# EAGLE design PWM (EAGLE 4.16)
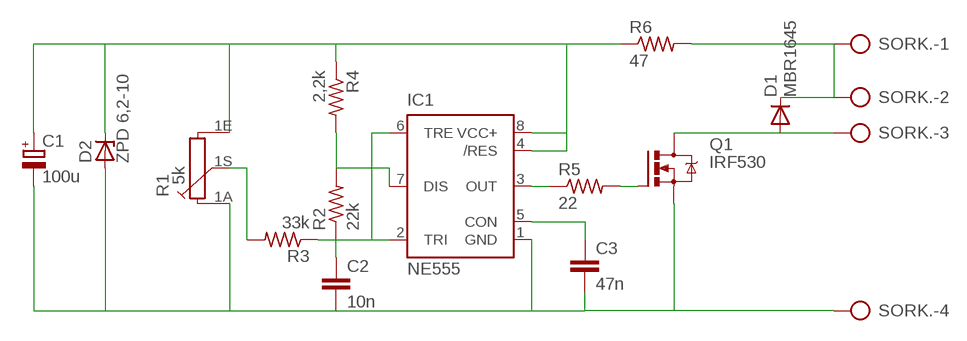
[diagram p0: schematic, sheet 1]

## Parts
C1  100u  CPOL-EUE5-13  [E5-13]
C2  10n  C-EU050-035X075  [C050-035X075]
C3  47n  C-EU050-035X075  [C050-035X075]
D1  MBR1645  MBR750  [TO220AC]
D2  ZPD 6,2-10  ZPD  [DO35Z10]
IC1  NE555  [DIL-08]
Q1  IRF530  [TO220BV]
R1  5k  PC16S  [PC16S]
R2  22k  R-US_0204/7  [0204/7]
R3  33k  R-US_0204/7  [0204/7]
R4  2,2k  R-US_0204/7  [0204/7]
R5  22  R-US_0204/7  [0204/7]
R6  47  R-US_0204/7  [0204/7]
SORK.  AK300/4  [AK300/4]

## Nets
N$1: IC1.7(DIS) R2.2 R4.2
N$3: D1.C R6.2 SORK..1 SORK..2
N$4: D1.A Q1.D SORK..3
N$5: C2.1 IC1.2(TRI) IC1.6(TRE) R2.1 R3.1
N$6: R1.1S R3.2
N$7: C1.- C2.2 C3.2 D2.A IC1.1(GND) Q1.S R1.1A SORK..4
N$8: IC1.3(OUT) R5.1
N$9: Q1.G R5.2
N$10: C3.1 IC1.5(CON)
N$12: C1.+ D2.C IC1.4(/RES) IC1.8(VCC+) R1.1E R4.1 R6.1

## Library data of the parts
C1 = rcl:CPOL-EU: POLARIZED CAPACITOR, European symbol
C2 C3 = rcl:C-EU: CAPACITOR, European symbol
D1 = diode:MBR750: DIODE
D2 = diode:ZPD: Z DIODE
IC1 = st-microelectronics:NE555: General purpose bipolar Timer
Q1 = transistor-power:IRF530: HEXFET Power MOSFET
R1 = piher:PC16S: POTENTIOMETER single carbon potentiometer, 16 mm, S3ROH
R2-R6 = rcl:R-US_: RESISTOR, American symbol
SORK. = con-ptr500:AK300/4: CONNECTOR

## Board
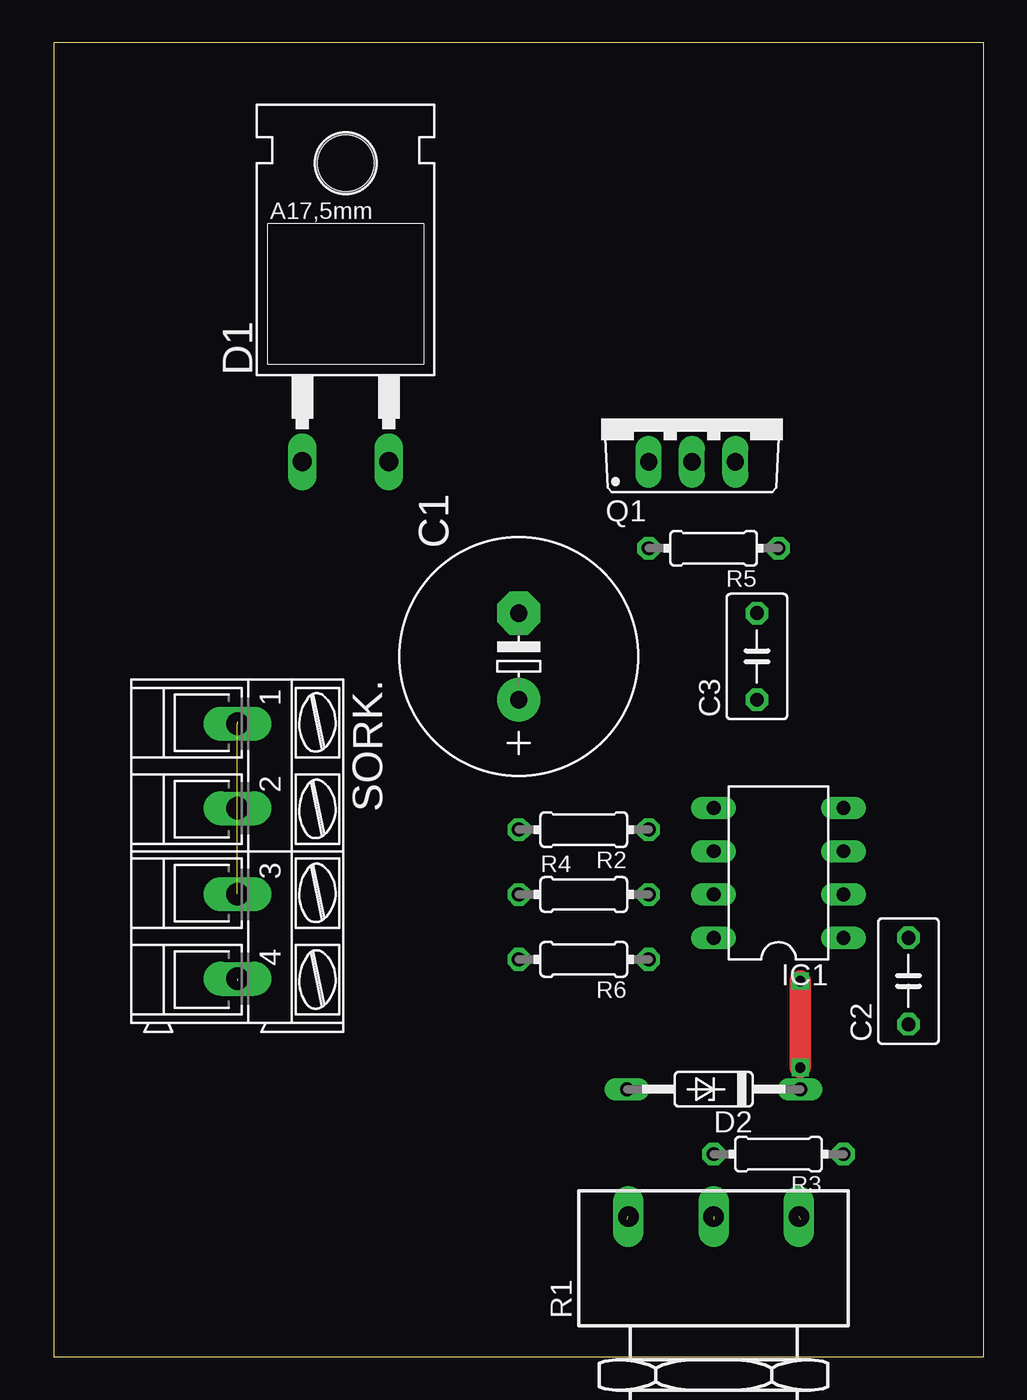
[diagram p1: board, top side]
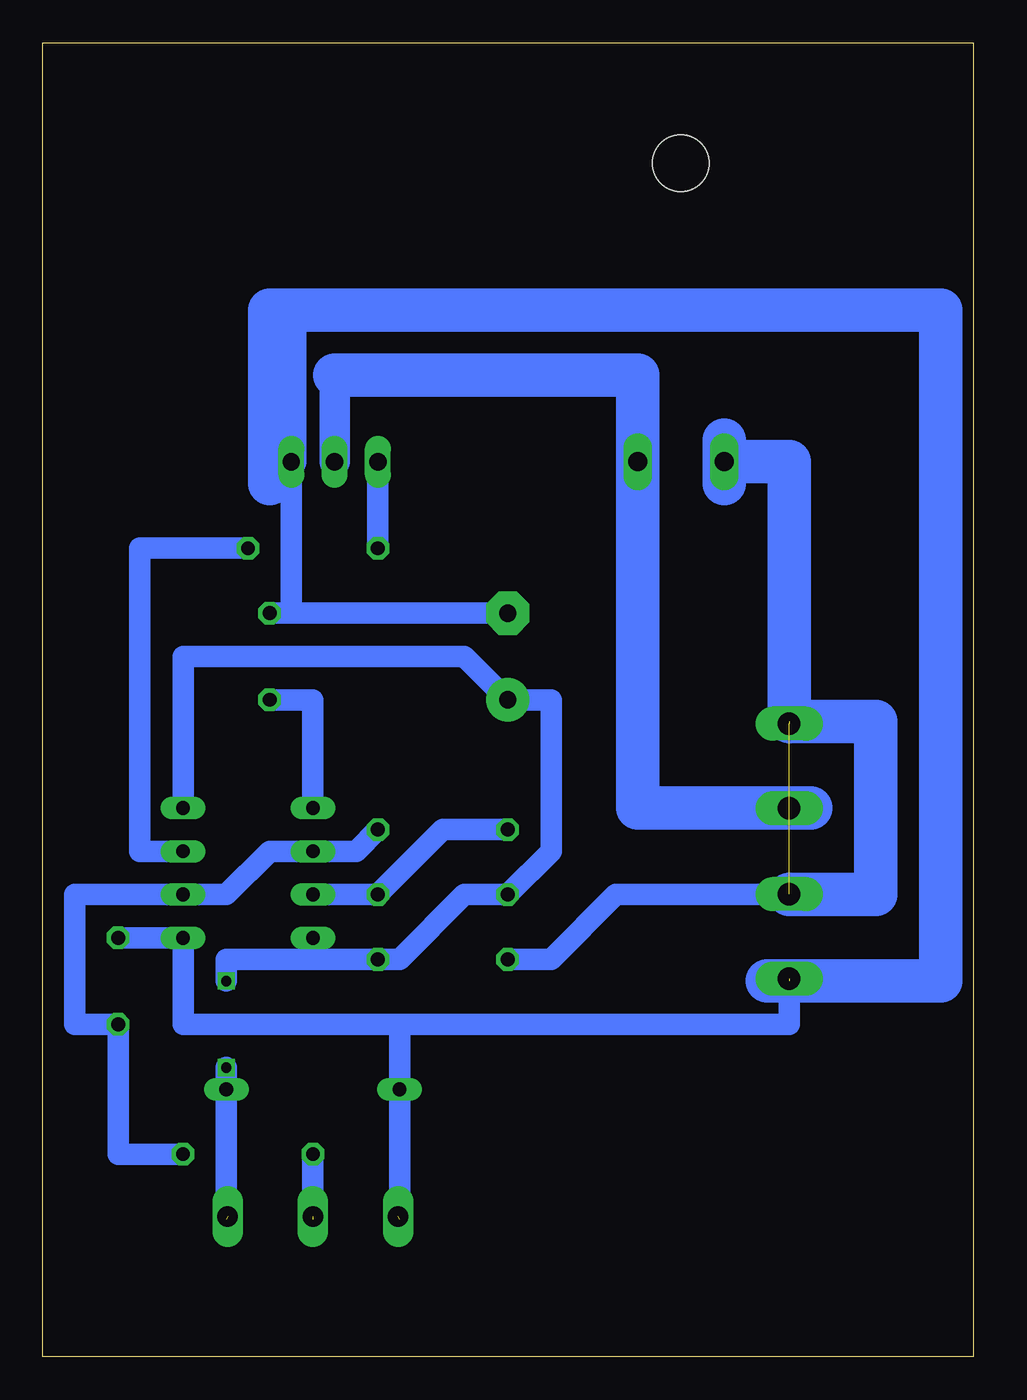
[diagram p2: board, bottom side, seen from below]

Size 54.59 x 77.14 mm. Coordinates in mm from the lower left corner, seen from the top.
Outline: 0,0 54.59,0 54.59,77.14 0,77.14 0,0
Copper layers (1*16): Top 0.035mm / dielectric 1.5mm / Bottom 0.035mm
Design rules "default": minimum track width 10mil, minimum drill 24mil, track to track 8mil, track to pad 8mil, pad to pad 8mil, via to via 8mil, smd to smd 8mil, copper to edge 40mil, drill to drill 8mil, minimum pad ring 10mil, minimum via ring 8mil, stop-mask expansion 4mil, vias tented up to drill 0mil, thermal gap 10mil

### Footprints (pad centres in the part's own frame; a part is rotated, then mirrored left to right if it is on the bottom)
E5-13 = drill 1.016 pad 2.54 round: + -2.54,0 | drill 1.016 pad 2.54 octagon: - 2.54,0
C050-035X075 = drill 0.813 octagon: 1 -2.54,0; 2 2.54,0
TO220AC = drill 1.118 long: A 2.54,-6.35; C -2.54,-6.35 | hole 3.302: 0,11.176
DO35Z10 = drill 0.813 long: A 5.08,0; C -5.08,0
DIL-08 = drill 0.813 long: 1 -3.81,-3.81; 2 -1.27,-3.81; 3 1.27,-3.81; 4 3.81,-3.81; 5 3.81,3.81; 6 1.27,3.81; 7 -1.27,3.81; 8 -3.81,3.81
TO220BV = drill 1.016 long: D 0,-2.54; G -2.54,-2.54; S 2.54,-2.54
PC16S = drill 1.2 long: 1A -5,6.5; 1E 5,6.5; 1S 0,6.5
0204/7 = drill 0.813 octagon: 1 -3.81,0; 2 3.81,0
AK300/4 = drill 1.321 long: 1 -7.493,0; 2 -2.515,0; 3 2.515,0; 4 7.493,0

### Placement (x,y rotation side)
C1  27.3,41.11 90 top
C2  47n  [C050-035X075]  50.16,22.06 90 top
C3  41.27,41.11 90 top
D1  MBR750  [TO220AC]  17.14,58.89 0 top
D2  ZPD 6,2  [DO35Z10]  38.73,15.71 180 top
IC1  42.54,28.41 90 top
Q1  37.46,55.08 0 top
R1  38.73,1.74 0 top
R2  31.11,30.95 180 top
R3  42.54,11.9 180 top
R4  31.11,27.14 0 top
R5  38.73,47.46 180 top
R6  31.11,23.33 180 top
SORK.  10.79,29.68 270 top

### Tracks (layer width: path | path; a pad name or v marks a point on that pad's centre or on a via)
N$1
  Bottom 1.27: IC1.7 R4.2 31.11,30.95 R2.2
N$3  (2 unrouted)
  Bottom 1.27: 10.79,27.14 20.95,27.14 24.76,23.33 R6.2
  Bottom 2.54: D1.C 10.79,52.54 10.79,37.3 5.71,37.3 5.71,27.14 10.79,27.14
N$4  (1 unrouted)
  Bottom 1.778: 19.68,32.22 10.79,32.22 | 37.46,57.62 Q1.D
  Bottom 2.54: 37.46,57.62 19.68,57.62 D1.A 19.68,32.22 9.52,32.22
N$5
  Bottom 1.27: R3.1 50.16,11.9 C2.1 52.7,19.52 52.7,27.14 IC1.2 43.81,27.14 41.27,29.68 IC1.6 36.19,29.68 R2.1
N$6  (1 unrouted)
  Bottom 1.27: 38.73,8.09 R3.2
N$7  (2 unrouted)
  Bottom 1.27: C2.2 IC1.1 46.35,19.52 33.65,19.52 | 40,43.65 C1.- | 40,43.65 C3.2 | D2.A 33.65,8.09 D2.A | 10.79,22.06 10.79,19.52 33.65,19.52 | 33.65,19.52 D2.A | Q1.S 40,43.65
  Bottom 1.778: 40,61.43 Q1.S
  Bottom 2.54: 12.06,22.06 10.79,22.06 1.9,22.06 1.9,61.43 40,61.43 41.27,61.43 41.27,53.81 | 41.27,53.81 41.27,52.54 | 41.27,53.81 41.27,51.27
N$8
  Bottom 1.27: R5.1 48.89,47.46 48.89,29.68 IC1.3
N$9
  Bottom 1.27: R5.2 Q1.G
N$10
  Bottom 1.27: IC1.5 38.73,38.57 C3.1
N$11
  Bottom 2.54: 14.6,51.27 14.6,53.81
N$12  (via drill 0.6)  (1 unrouted)
  Top 1.27: v43.81,16.98 v43.81,22.06
  Bottom 1.27: 38.73,23.33 R6.1 33.65,23.33 29.84,27.14 R4.1 24.76,29.68 24.76,38.57 C1.+ 29.84,41.11 46.35,41.11 IC1.4 | 38.73,23.33 IC1.8 | 43.81,8.09 D2.C v43.81,16.98 | 38.73,23.33 43.81,23.33 v43.81,22.06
